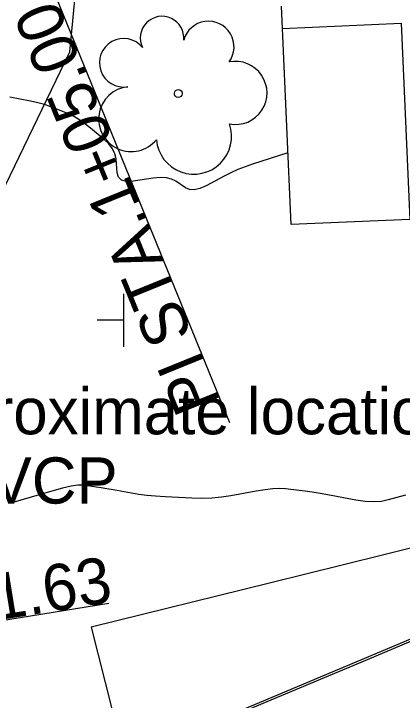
# Model space of a CAD drawing. Extents: x 2030588 to 2035216, y 462285 to 465007.
# Drawn here: x 2031296.08 to 2031319.62, y 464275.55 to 464317.16 of the extents above; entities that cross this region are included whole.
import ezdxf

# ---------------------------------------------------------------- set-up
doc = ezdxf.new("R2010")
doc.units = 0
for name, color, linetype in [('BD_X_Building', 7, 'Continuous'), ('BD_X_Porch_or_Deck', 7, 'Continuous'), ('DT_X_Contour_Minor', 7, 'Continuous'), ('GE_P_Alignment_100_Cardinal_Points', 7, 'Continuous'), ('GE_X_Alignment_100_Cardinal_Points', 7, 'Continuous'), ('MD_P_CONST_LIMITS', 7, 'Continuous'), ('SN_X_Public', 7, 'Continuous'), ('SV_X_Text', 7, 'Continuous'), ('UT_X_Electric', 7, 'Continuous'), ('VG_X_Cells', 7, 'Continuous')]:
    doc.layers.add(name, color=color, linetype=linetype)

msp = doc.modelspace()

# ---------------------------------------------------------------- linework, layer by layer
at = {"layer": 'BD_X_Building'}
for points in [[(2031312.882, 464304.375), (2031312.354, 464316.266), (2031311.814, 464328.452), (2031319.655, 464328.798), (2031324.902, 464329.03), (2031333.154, 464329.394), (2031342.968, 464329.827), (2031348.498, 464330.072), (2031349.056, 464317.507), (2031343.615, 464317.267), (2031344.126, 464305.755), (2031336.745, 464305.429), (2031327.934, 464305.04), (2031320.082, 464304.693)], [(2031303.716, 464268.313), (2031324.142, 464273.389), (2031330.91, 464275.071), (2031327.975, 464286.726), (2031322.779, 464285.435), (2031318.414, 464284.351), (2031311.579, 464282.652), (2031300.781, 464279.969)]]:
    msp.add_lwpolyline(points, close=True, dxfattribs=at)
at = {"layer": 'BD_X_Porch_or_Deck'}
for p, q in [((2031312.354, 464316.266), (2031319.556, 464316.586)), ((2031319.556, 464316.586), (2031320.082, 464304.693))]:
    msp.add_line(p, q, dxfattribs=at)
at = {"layer": 'DT_X_Contour_Minor'}
for points in [[(2031312.689, 464308.724), (2031310.552, 464308.041), (2031310.101, 464307.885), (2031309.662, 464307.713), (2031309.237, 464307.522), (2031308.824, 464307.314), (2031307.742, 464306.736), (2031307.358, 464306.566), (2031307.021, 464306.488), (2031306.73, 464306.502), (2031306.486, 464306.609), (2031305.894, 464307.017), (2031305.642, 464307.143), (2031305.331, 464307.214), (2031304.962, 464307.23), (2031304.533, 464307.191), (2031303.31, 464307.015), (2031302.906, 464306.996), (2031302.61, 464307.074), (2031302.423, 464307.248), (2031302.344, 464307.517), (2031302.28, 464308.363), (2031302.216, 464308.676), (2031302.072, 464308.98), (2031301.848, 464309.275), (2031301.545, 464309.562), (2031300.63, 464310.314), (2031300.294, 464310.576), (2031299.971, 464310.796), (2031299.663, 464310.975), (2031299.369, 464311.113), (2031298.602, 464311.426), (2031298.292, 464311.54), (2031297.938, 464311.65), (2031297.538, 464311.753), (2031297.094, 464311.851), (2031295.851, 464312.106)], [(2031319.802, 464287.982), (2031318.766, 464287.686), (2031318.351, 464287.603), (2031317.885, 464287.575), (2031317.366, 464287.602), (2031316.796, 464287.684), (2031315.205, 464287.976), (2031314.643, 464288.076), (2031314.152, 464288.158), (2031313.731, 464288.222), (2031313.381, 464288.266), (2031312.54, 464288.362), (2031312.192, 464288.379), (2031311.78, 464288.362), (2031311.304, 464288.309), (2031310.764, 464288.221), (2031309.237, 464287.938), (2031308.66, 464287.849), (2031308.075, 464287.795), (2031307.481, 464287.775), (2031306.878, 464287.789), (2031305.26, 464287.874), (2031304.677, 464287.912), (2031304.142, 464287.96), (2031303.656, 464288.02), (2031303.217, 464288.091), (2031302.112, 464288.294), (2031301.722, 464288.365), (2031301.379, 464288.423), (2031301.085, 464288.47), (2031300.838, 464288.504), (2031300.243, 464288.581), (2031299.96, 464288.58), (2031299.558, 464288.519), (2031299.036, 464288.4), (2031298.394, 464288.221), (2031296.523, 464287.666), (2031295.902, 464287.484)]]:
    msp.add_lwpolyline(points, dxfattribs=at)
at = {"layer": 'GE_P_Alignment_100_Cardinal_Points'}
msp.add_line((2031292.185, 464334.061), (2031309.157, 464292.389), dxfattribs=at)
at = {"layer": 'GE_X_Alignment_100_Cardinal_Points'}
msp.add_line((2031257.417, 464274.275), (2031301.838, 464281.437), dxfattribs=at)
at = {"layer": 'MD_P_CONST_LIMITS'}
for points in [[(2031299.488, 464314.858), (2031300.288, 464323.242), (2031312.015, 464333.369), (2031323.227, 464340.901), (2031335.72, 464342.732)], [(2031304.871, 464099.462), (2031318.532, 464105.655), (2031311.904, 464118.546), (2031304.38, 464141.463), (2031297.225, 464164.67), (2031295.574, 464189.665), (2031297.675, 464215.284), (2031293.386, 464239.179), (2031288.691, 464262.969), (2031290.634, 464288.11), (2031294.17, 464303.872), (2031299.488, 464314.858)]]:
    msp.add_lwpolyline(points, dxfattribs=at)
at = {"layer": 'SN_X_Public'}
for p, q in [((2031302.74, 464300.179), (2031302.74, 464296.979)), ((2031302.74, 464298.579), (2031301.14, 464298.579)), ((2031302.739, 464298.58), (2031302.739, 464298.58))]:
    msp.add_line(p, q, dxfattribs=at)
at = {"layer": 'UT_X_Electric'}
for points in [[(2031287.96, 464266.694), (2031305.634, 464273.172), (2031320.893, 464279.587), (2031328.109, 464282.63)], [(2031288.464, 464265.862), (2031317.519, 464278.022), (2031322.908, 464280.293)]]:
    msp.add_lwpolyline(points, dxfattribs=at)
at = {"layer": 'VG_X_Cells'}
for centre, major_axis, start_param, end_param in [((2031305.067, 464315.692), (0.879, -0.98), 0.735036, 4.434601), ((2031307.877, 464315.153), (1.036, -1.156), 0.208709, 3.720445), ((2031302.742, 464314.189), (-0.982, 1.095), 4.66298, 8.860125), ((2031309.511, 464312.361), (1.278, -1.425), 5.362573, 8.893624), ((2031303.198, 464310.776), (-1.318, 1.469), 5.659661, 9.576206), ((2031306.997, 464309.72), (1.524, -1.701), 4.068299, 7.463132)]:
    msp.add_ellipse(centre, major_axis=major_axis, ratio=0.999987, start_param=start_param, end_param=end_param, dxfattribs=at)
msp.add_ellipse((2031306.051, 464312.325), major_axis=(-0.16, 0.179), ratio=0.999987, dxfattribs=at)

# ---------------------------------------------------------------- texts
at = {"layer": 'GE_P_Alignment_100_Cardinal_Points'}
for s, p in [('1+05.00', (2031303.769, 464305.508)), (' STA. ', (2031307.333, 464296.755)), ('PI', (2031308.612, 464293.614))]:
    msp.add_text(s, height=2.7997, rotation=112.1592, dxfattribs=at).set_placement(p)
at = {"layer": 'GE_X_Alignment_100_Cardinal_Points'}
msp.add_text('147+91.63', height=2.7997, rotation=9.1587, dxfattribs=at).set_placement((2031284.588, 464278.693))
at = {"layer": 'SV_X_Text'}
for s, height, p in [('Approximate location of', 2.79972, (2031288.147, 464291.668)), ('10" VCP ', 2.7997, (2031288.147, 464287.469))]:
    msp.add_text(s, height=height, rotation=359.9993, dxfattribs=at).set_placement(p)

doc.saveas('drawing.dxf')
